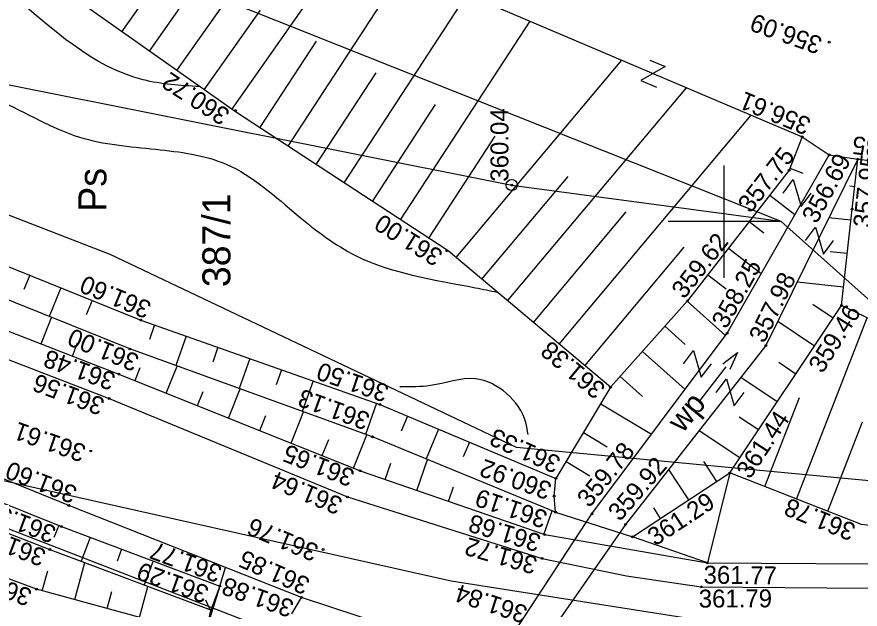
# Model space of a CAD drawing. Extents: x 4635329 to 4651863, y 5356628 to 5367582.
# Drawn here: x 4651155.45 to 4651193.08, y 5356689.07 to 5356715.48 of the extents above; entities that cross this region are included whole.
import ezdxf

# ---------------------------------------------------------------- set-up
doc = ezdxf.new("R2010")
doc.units = 0
for name, color, linetype in [('Level 12', 7, 'Continuous'), ('Level 20', 7, 'Continuous'), ('Level 22', 7, 'Continuous'), ('Level 24', 7, 'Continuous'), ('Level 29', 7, 'Continuous'), ('Level 4', 7, 'Continuous'), ('Level 44', 7, 'Continuous'), ('Level 45', 7, 'Continuous'), ('Level 46', 7, 'Continuous'), ('Level 48', 7, 'Continuous'), ('Level 5', 7, 'Continuous'), ('Level 50', 7, 'Continuous'), ('Level 51', 7, 'Continuous'), ('Level 53', 7, 'Continuous'), ('Level 60', 7, 'Continuous'), ('Level 7', 7, 'Continuous')]:
    doc.layers.add(name, color=color, linetype=linetype)

msp = doc.modelspace()

# ---------------------------------------------------------------- linework, layer by layer
at = {"layer": 'Level 20'}
for points in [[(4651122.765, 5356712.887), (4651146.685, 5356703.427), (4651159.565, 5356698.457), (4651170.205, 5356694.067), (4651178.895, 5356691.327), (4651182.663, 5356690.554), (4651185.995, 5356690.057), (4651193.465, 5356690.007), (4651201.855, 5356691.047)], [(4651201.455, 5356686.167), (4651194.035, 5356685.457), (4651185.485, 5356685.017), (4651181.21, 5356685.664), (4651178.315, 5356686.247), (4651168.145, 5356689.587), (4651157.765, 5356693.687), (4651144.895, 5356698.917), (4651120.155, 5356708.837)], [(4651164.505, 5356690.097), (4651164.761, 5356690.924)], [(4651164.505, 5356690.097), (4651163.815, 5356687.907), (4651153.195, 5356678.107)], [(4651167.725, 5356688.857), (4651168.145, 5356689.587)]]:
    msp.add_lwpolyline(points, dxfattribs=at)
at = {"layer": 'Level 22'}
for points in [[(4651175.165, 5356684.237), (4651181.115, 5356693.317)], [(4651182.615, 5356692.847), (4651176.225, 5356683.677)]]:
    msp.add_lwpolyline(points, dxfattribs=at)
at = {"layer": 'Level 24'}
msp.add_line((4651163.871, 5356689.482), (4651164.085, 5356688.997), dxfattribs=at)
at = {"layer": 'Level 29'}
msp.add_line((4651179.485, 5356693.387), (4651182.925, 5356692.287), dxfattribs=at)
at = {"layer": 'Level 4'}
for p, q in [((4651155.671, 5356719.834), (4651189.548, 5356706.371)), ((4651159.614, 5356704.887), (4651123.689, 5356718.747)), ((4651130.975, 5356717.257), (4651177.535, 5356707.977)), ((4651177.535, 5356707.977), (4651189.548, 5356706.371)), ((4651189.548, 5356706.371), (4651199.767, 5356697.217)), ((4651177.75, 5356696.277), (4651159.614, 5356704.887)), ((4651169.904, 5356686.914), (4651125.563, 5356703.993)), ((4651174.835, 5356690.307), (4651125.405, 5356701.397)), ((4651196.006, 5356694.549), (4651177.75, 5356696.277)), ((4651206.08, 5356685.424), (4651174.835, 5356690.307))]:
    msp.add_line(p, q, dxfattribs=at)
at = {"layer": 'Level 44'}
for centre in [(4651191.705, 5356714.347), (4651165.205, 5356711.297), (4651190.495, 5356710.127), (4651191.705, 5356709.327), (4651192.985, 5356709.127), (4651189.915, 5356708.637), (4651177.535, 5356707.977), (4651192.725, 5356706.907), (4651174.635, 5356705.047), (4651185.385, 5356702.817), (4651192.255, 5356702.607), (4651160.975, 5356701.957), (4651187.145, 5356701.367), (4651160.495, 5356700.667), (4651188.875, 5356700.817), (4651159.995, 5356699.547), (4651181.945, 5356698.957), (4651159.565, 5356698.457), (4651171.645, 5356698.197), (4651171.315, 5356696.747), (4651158.745, 5356696.117), (4651170.765, 5356695.237), (4651179.505, 5356694.897), (4651187.265, 5356695.137), (4651170.205, 5356694.067), (4651179.425, 5356694.107), (4651157.765, 5356693.687), (4651179.485, 5356693.387), (4651181.115, 5356693.317), (4651157.435, 5356692.747), (4651182.615, 5356692.847), (4651179.005, 5356692.387), (4651182.925, 5356692.287), (4651156.915, 5356691.727), (4651169.115, 5356691.727), (4651178.895, 5356691.327), (4651186.265, 5356691.127), (4651164.505, 5356690.097), (4651185.995, 5356690.057), (4651156.325, 5356689.957), (4651168.145, 5356689.587)]:
    msp.add_circle(centre, 0.04, dxfattribs=at)
at = {"layer": 'Level 46'}
for points in [[(4651163.601, 5356712.367), (4651161.083, 5356712.669), (4651155.2, 5356716.489), (4651152.41, 5356718.49), (4651149.802, 5356719.218), (4651148.043, 5356719.036), (4651147.174, 5356719.006)], [(4651153.387, 5356712.298), (4651154.663, 5356711.755), (4651158.242, 5356710.118), (4651161.638, 5356709.572), (4651164.792, 5356708.905), (4651168.007, 5356706.601), (4651170.554, 5356704.842), (4651175.916, 5356703.398), (4651176.89, 5356703.203)], [(4651178.265, 5356696.858), (4651178.16, 5356697.395), (4651175.916, 5356699.335), (4651173.914, 5356699.032), (4651172.58, 5356698.972), (4651172.542, 5356698.971)], [(4651156.765, 5356687.524), (4651156.246, 5356687.701), (4651149.028, 5356687.58), (4651145.813, 5356689.823), (4651143.266, 5356691.036), (4651138.778, 5356692.066), (4651136.17, 5356693.037), (4651136.124, 5356693.062)]]:
    msp.add_spline(points, degree=3, dxfattribs=at)
at = {"layer": 'Level 48'}
for p, q in [((4651160.135, 5356714.808), (4651164.584, 5356721.124)), ((4651162.588, 5356713.08), (4651167.412, 5356719.93)), ((4651165.04, 5356711.353), (4651170.24, 5356718.735)), ((4651167.549, 5356709.708), (4651172.743, 5356717.671)), ((4651161.361, 5356713.944), (4651163.68, 5356717.236)), ((4651170.062, 5356708.069), (4651175.548, 5356716.48)), ((4651163.814, 5356712.217), (4651166.32, 5356715.775)), ((4651172.575, 5356706.43), (4651178.352, 5356715.288)), ((4651166.293, 5356710.527), (4651168.817, 5356714.397)), ((4651175.054, 5356704.746), (4651182.447, 5356713.547)), ((4651168.806, 5356708.889), (4651171.476, 5356712.982)), ((4651177.351, 5356702.816), (4651185.334, 5356712.32)), ((4651171.318, 5356707.25), (4651174.134, 5356711.567)), ((4651179.648, 5356700.887), (4651188.221, 5356711.093)), ((4651173.831, 5356705.611), (4651176.793, 5356710.151)), ((4651189.951, 5356708.729), (4651190.528, 5356708.505)), ((4651176.202, 5356703.781), (4651180.046, 5356708.357)), ((4651192.841, 5356707.899), (4651192.622, 5356707.925)), ((4651189.054, 5356707.531), (4651190.176, 5356706.658)), ((4651178.499, 5356701.851), (4651182.639, 5356706.779)), ((4651188.133, 5356706.348), (4651188.778, 5356705.846)), ((4651192.671, 5356706.409), (4651191.693, 5356706.516)), ((4651180.796, 5356699.922), (4651185.231, 5356705.201)), ((4651187.212, 5356705.164), (4651188.67, 5356704.029)), ((4651192.508, 5356704.918), (4651191.747, 5356705.001)), ((4651186.29, 5356703.98), (4651187.104, 5356703.347)), ((4651156.019, 5356703.954), (4651155.761, 5356703.314)), ((4651192.345, 5356703.427), (4651190.277, 5356703.653)), ((4651157.411, 5356703.394), (4651156.895, 5356702.114)), ((4651158.802, 5356702.833), (4651158.544, 5356702.194)), ((4651185.368, 5356702.798), (4651187.076, 5356701.275)), ((4651191.88, 5356702.045), (4651190.979, 5356702.647)), ((4651198.845, 5356699.427), (4651192.255, 5356702.607)), ((4651156.529, 5356700.895), (4651156.989, 5356702.077)), ((4651161.595, 5356701.739), (4651161.365, 5356701.087)), ((4651191.047, 5356700.798), (4651189.407, 5356701.893)), ((4651190.245, 5356693.976), (4651193.393, 5356702.058)), ((4651184.37, 5356701.678), (4651185.272, 5356700.874)), ((4651163.009, 5356701.24), (4651162.546, 5356699.924)), ((4651157.927, 5356700.351), (4651158.154, 5356700.934)), ((4651164.424, 5356700.742), (4651164.19, 5356700.077)), ((4651165.839, 5356700.243), (4651165.366, 5356698.902)), ((4651183.372, 5356700.558), (4651185.271, 5356698.865)), ((4651160.721, 5356699.257), (4651160.953, 5356699.837)), ((4651162.113, 5356698.699), (4651162.596, 5356699.906)), ((4651190.213, 5356699.551), (4651189.448, 5356700.062)), ((4651167.254, 5356699.744), (4651167.015, 5356699.068)), ((4651168.668, 5356699.246), (4651168.187, 5356697.88)), ((4651182.374, 5356699.438), (4651183.371, 5356698.549)), ((4651189.38, 5356698.303), (4651187.754, 5356699.39)), ((4651163.506, 5356698.142), (4651163.757, 5356698.768)), ((4651164.899, 5356697.585), (4651165.418, 5356698.883)), ((4651188.831, 5356694.527), (4651190.381, 5356698.507)), ((4651171.498, 5356698.249), (4651171.008, 5356696.858)), ((4651181.504, 5356698.224), (4651183.77, 5356696.862)), ((4651166.291, 5356697.027), (4651166.56, 5356697.7)), ((4651167.684, 5356696.47), (4651168.24, 5356697.861)), ((4651172.884, 5356697.677), (4651172.602, 5356697.005)), ((4651188.547, 5356697.056), (4651187.686, 5356697.631)), ((4651191.643, 5356693.432), (4651193.195, 5356697.418)), ((4651170.469, 5356695.355), (4651171.063, 5356696.839)), ((4651174.267, 5356697.096), (4651173.708, 5356695.763)), ((4651180.732, 5356696.938), (4651181.799, 5356696.297)), ((4651187.714, 5356695.809), (4651185.895, 5356697.023)), ((4651169.076, 5356695.913), (4651169.364, 5356696.631)), ((4651175.65, 5356696.515), (4651175.373, 5356695.854)), ((4651173.299, 5356694.361), (4651173.774, 5356695.735)), ((4651171.881, 5356694.851), (4651172.133, 5356695.579)), ((4651179.959, 5356695.652), (4651181.015, 5356695.017)), ((4651186.686, 5356694.757), (4651186.101, 5356695.649)), ((4651182.925, 5356692.287), (4651187.265, 5356695.137)), ((4651185.433, 5356693.934), (4651184.538, 5356695.296)), ((4651174.717, 5356693.87), (4651174.94, 5356694.517)), ((4651178.969, 5356692.399), (4651179.333, 5356693.45)), ((4651184.179, 5356693.11), (4651183.87, 5356693.581)), ((4651157.316, 5356692.795), (4651157.103, 5356692.265)), ((4651158.719, 5356692.266), (4651158.319, 5356691.198)), ((4651186.265, 5356691.127), (4651182.925, 5356692.287)), ((4651160.124, 5356691.739), (4651159.924, 5356691.204)), ((4651161.529, 5356691.213), (4651161.127, 5356690.141)), ((4651158.028, 5356689.491), (4651158.479, 5356691.138)), ((4651156.581, 5356689.887), (4651156.825, 5356690.778)), ((4651160.921, 5356688.699), (4651161.299, 5356690.077)), ((4651159.475, 5356689.095), (4651159.682, 5356689.851))]:
    msp.add_line(p, q, dxfattribs=at)
for points in [[(4651181.945, 5356698.957), (4651174.695, 5356705.047), (4651165.205, 5356711.237), (4651153.535, 5356719.457), (4651148.105, 5356722.037), (4651132.135, 5356729.877)], [(4651123.975, 5356716.737), (4651147.825, 5356707.257), (4651160.975, 5356701.957), (4651171.645, 5356698.197), (4651179.505, 5356694.897)], [(4651179.485, 5356693.387), (4651171.315, 5356696.747), (4651160.495, 5356700.667), (4651147.535, 5356705.877), (4651123.495, 5356715.267)], [(4651122.975, 5356713.937), (4651147.035, 5356704.587), (4651159.995, 5356699.547), (4651170.765, 5356695.237), (4651179.005, 5356692.387)], [(4651190.495, 5356710.127), (4651189.915, 5356708.637), (4651185.385, 5356702.817), (4651181.945, 5356698.957), (4651179.505, 5356694.897)], [(4651187.265, 5356695.137), (4651192.255, 5356702.607), (4651192.725, 5356706.907), (4651192.985, 5356709.127)], [(4651119.725, 5356707.867), (4651145.105, 5356697.697), (4651157.435, 5356692.747), (4651164.505, 5356690.097)], [(4651119.395, 5356706.647), (4651144.585, 5356696.527), (4651156.915, 5356691.727), (4651164.127, 5356689.012)], [(4651163.815, 5356687.907), (4651156.325, 5356689.957), (4651143.745, 5356694.647), (4651136.825, 5356697.727), (4651118.775, 5356705.457)], [(4651201.405, 5356691.717), (4651201.035, 5356692.627), (4651195.325, 5356692.587), (4651193.145, 5356692.847), (4651187.265, 5356695.137), (4651186.265, 5356691.127)], [(4651179.485, 5356693.387), (4651179.425, 5356694.107), (4651179.505, 5356694.897)], [(4651179.005, 5356692.387), (4651186.265, 5356691.127)], [(4651186.265, 5356691.127), (4651193.521, 5356691.081), (4651201.405, 5356691.717)], [(4651164.505, 5356690.097), (4651164.085, 5356688.997), (4651163.815, 5356687.907)]]:
    msp.add_lwpolyline(points, dxfattribs=at)
at = {"layer": 'Level 50'}
for p, q in [((4651169.765, 5356718.937), (4651190.495, 5356710.127)), ((4651190.495, 5356710.127), (4651191.705, 5356709.327)), ((4651187.145, 5356701.367), (4651191.705, 5356709.327)), ((4651191.705, 5356709.327), (4651192.985, 5356709.127)), ((4651192.985, 5356709.127), (4651188.875, 5356700.817)), ((4651192.985, 5356709.127), (4651202.845, 5356708.137)), ((4651181.115, 5356693.317), (4651187.145, 5356701.367)), ((4651188.875, 5356700.817), (4651182.615, 5356692.847)), ((4651186.953, 5356700), (4651187.603, 5356700.507)), ((4651187.603, 5356700.507), (4651187.267, 5356699.753)), ((4651185.877, 5356698.302), (4651187.11, 5356699.877))]:
    msp.add_line(p, q, dxfattribs=at)
at = {"layer": 'Level 53'}
for p, q in [((4651183.693, 5356713.554), (4651184.384, 5356713.261)), ((4651184.384, 5356713.261), (4651183.303, 5356712.633)), ((4651183.303, 5356712.633), (4651183.994, 5356712.34)), ((4651189.645, 5356707.62), (4651190.096, 5356708.22)), ((4651190.096, 5356708.22), (4651190.445, 5356707.02)), ((4651190.445, 5356707.02), (4651190.896, 5356707.62)), ((4651190.645, 5356705.499), (4651191.096, 5356706.099)), ((4651191.096, 5356706.099), (4651191.445, 5356704.899)), ((4651191.445, 5356704.899), (4651191.896, 5356705.499)), ((4651185.197, 5356700.006), (4651185.65, 5356700.604)), ((4651185.65, 5356700.604), (4651185.994, 5356699.403)), ((4651185.994, 5356699.403), (4651186.447, 5356700.001)), ((4651186.663, 5356698.73), (4651187.114, 5356699.33)), ((4651187.114, 5356699.33), (4651187.463, 5356698.13)), ((4651187.463, 5356698.13), (4651187.914, 5356698.73))]:
    msp.add_line(p, q, dxfattribs=at)
at = {"layer": 'Level 60'}
for p, q in [((4651187.015, 5356703.847), (4651187.015, 5356708.847)), ((4651189.515, 5356706.347), (4651184.515, 5356706.347))]:
    msp.add_line(p, q, dxfattribs=at)
at = {"layer": 'Level 7'}
msp.add_circle((4651177.535, 5356707.977), 0.25, dxfattribs=at)

# ---------------------------------------------------------------- texts
at = {"layer": 'Level 12'}
msp.add_text('Ps', height=1.25, rotation=90, dxfattribs=at).set_placement((4651159.443, 5356706.786))
at = {"layer": 'Level 45'}
for s, rotation, p in [('356.09', 160.3721, (4651191.451, 5356714.543)), ('360.72', 146.8433, (4651165.018, 5356711.268)), ('356.61', 157.6009, (4651190.952, 5356710.921)), ('360.04', 90, (4651177.385, 5356708.127)), ('356.85', 172.8332, (4651196.037, 5356709.758)), ('357.75', 52.1273, (4651188.194, 5356706.682)), ('356.69', 61.5925, (4651191.145, 5356706.213)), ('357.95', 83.6699, (4651193.559, 5356706.053)), ('361.00', 148.0228, (4651174.526, 5356704.992)), ('359.62', 51.8519, (4651185.23, 5356702.857)), ('358.25', 60.7048, (4651187.108, 5356701.524)), ('357.98', 63.8526, (4651188.8, 5356700.887)), ('361.60', 157.6785, (4651161.51, 5356702.732)), ('359.46', 57.8466, (4651191.403, 5356699.537)), ('361.00', 157.7386, (4651160.967, 5356700.373)), ('361.38', 140.2633, (4651181.777, 5356698.988)), ('361.48', 160.1398, (4651159.912, 5356699.548)), ('361.50', 161.0015, (4651172.107, 5356699.027)), ('361.56', 159.4491, (4651159.423, 5356698.434)), ('361.13', 159.8793, (4651171.264, 5356697.778)), ('361.44', 56.5821, (4651188.168, 5356694.825)), ('361.61', 160.856, (4651158.593, 5356696.354)), ('361.33', 155.9132, (4651179.78, 5356695.821)), ('359.78', 50.8665, (4651181.001, 5356693.552)), ('361.65', 158.6214, (4651170.582, 5356695.242)), ('360.92', 160.2724, (4651179.38, 5356694.674)), ('359.92', 48.939, (4651182.363, 5356692.941)), ('361.60', 158.7202, (4651158.201, 5356694.493)), ('361.64', 157.5695, (4651170.046, 5356693.989)), ('361.19', 161.4351, (4651179.187, 5356693.406)), ('361.29', 33.2464, (4651183.935, 5356691.857)), ('361.58', 159.2614, (4651157.26, 5356692.726)), ('361.78', 158.2406, (4651192.95, 5356692.825)), ('361.76', 157.3506, (4651168.978, 5356691.9)), ('361.68', 163.2125, (4651178.895, 5356692.365)), ('361.16', 159.1455, (4651156.809, 5356691.689)), ('361.77', 159.8679, (4651164.664, 5356690.974)), ('361.72', 163.8023, (4651178.733, 5356691.366)), ('361.85', 156.2686, (4651168.592, 5356690.408)), ('362.13', 159.5732, (4651156.181, 5356689.919)), ('361.29', 160.1209, (4651164.077, 5356690.062)), ('361.77', 359.3178, (4651186.092, 5356690.204)), ('361.88', 160.5879, (4651167.87, 5356689.425)), ('361.84', 161.8643, (4651178.297, 5356689.173)), ('361.79', 0.2168, (4651185.881, 5356689.134))]:
    msp.add_text(s, height=0.8, rotation=rotation, dxfattribs=at).set_placement(p)
at = {"layer": 'Level 5'}
msp.add_text('387/1', height=1.25, rotation=90, dxfattribs=at).set_placement((4651164.978, 5356703.424))
at = {"layer": 'Level 51'}
msp.add_text('wp', height=1, rotation=50.5701, dxfattribs=at).set_placement((4651185.167, 5356696.887))

doc.saveas('drawing.dxf')
